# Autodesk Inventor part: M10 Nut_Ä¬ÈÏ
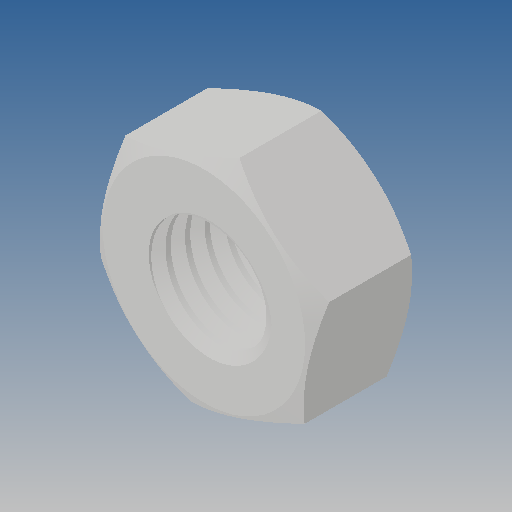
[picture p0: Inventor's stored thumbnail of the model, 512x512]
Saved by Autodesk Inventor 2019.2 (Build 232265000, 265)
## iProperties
Created: 2010-06
Part Number: M10 Nut_Ä¬ÈÏ
Material: Ogólny
Document SubType Name: Modeling
Designer: CADENGINEERING4
Density: 1 g/cm^3
Appearance: Domyślna
Author: CADENGINEERING4
Revision Number: ÈÎºÎ
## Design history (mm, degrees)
feature "NONE"
node "Bryła1"
